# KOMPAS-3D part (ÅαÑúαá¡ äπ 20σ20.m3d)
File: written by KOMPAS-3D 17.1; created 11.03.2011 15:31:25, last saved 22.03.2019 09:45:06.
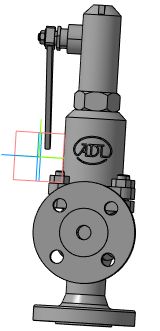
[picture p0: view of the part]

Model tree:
1. Плоскость XY
2. Плоскость ZX
3. Плоскость ZY
4. Ось X
5. Ось Y
6. Ось Z
7. Начало координат
8. Операция без истории:2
